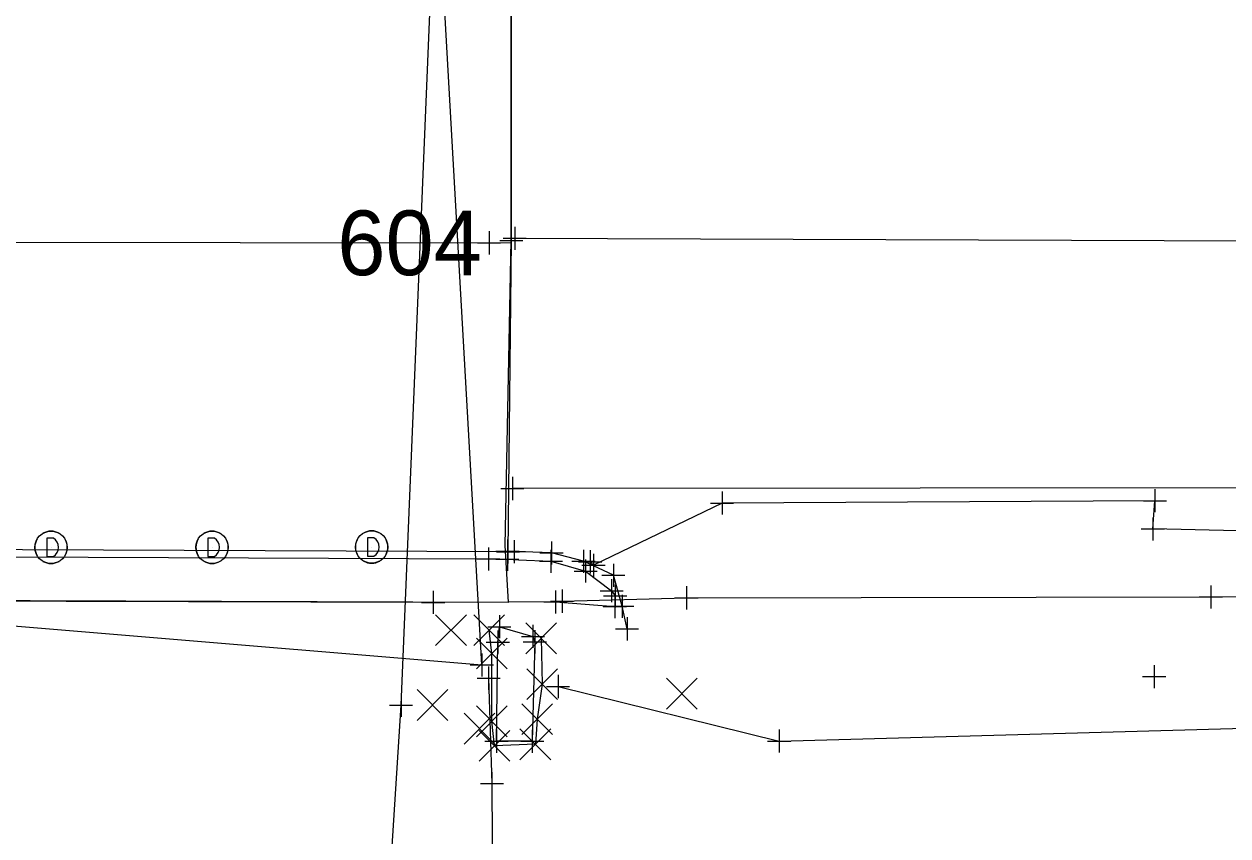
# Model space of a CAD drawing. Extents: x 146022 to 147632, y 437624 to 440659.
# Drawn here: x 147067.5 to 147119.5, y 438601.8 to 438636.9 of the extents above; entities that cross this region are included whole.
import ezdxf

# ---------------------------------------------------------------- set-up
doc = ezdxf.new("R2010")
doc.units = 0
for name, color, linetype in [('_CIVIL_CONSTRUCTION', 7, 'Continuous'), ('BR_P_Rail_Object', 7, 'Continuous'), ('Default', 7, 'Continuous'), ('DR_P_Paved_Gutter', 7, 'Continuous'), ('DR_X_Cells', 7, 'Continuous'), ('DT_X_Triangles', 7, 'Continuous'), ('GE_P_Alignment_100_Bearings', 7, 'Continuous'), ('GE_P_Alignment_100_Cardinal_Points', 7, 'Continuous'), ('GE_P_Alignment_100_Stations', 7, 'Continuous'), ('PF_X_Ground_Line', 7, 'Continuous'), ('PV_P_Curb', 7, 'Continuous'), ('RD_P_Anchor_Assembly', 7, 'Continuous'), ('RD_P_GR_Lt_Replaced', 7, 'Continuous'), ('SC_Scratch3', 7, 'Continuous'), ('SH_Text', 7, 'Continuous'), ('SV_X_Terrain_Boundary', 7, 'Continuous'), ('UT_X_Electric', 7, 'Continuous')]:
    doc.layers.add(name, color=color, linetype=linetype)

msp = doc.modelspace()

# ---------------------------------------------------------------- linework, layer by layer
at = {"layer": '_CIVIL_CONSTRUCTION'}
for p, q in [((147085.264, 438610.058), (147086.597, 438611.393)), ((147085.264, 438611.393), (147086.597, 438610.058)), ((147086.916, 438610.056), (147088.249, 438611.391)), ((147086.916, 438611.391), (147088.249, 438610.056)), ((147089.168, 438609.706), (147090.501, 438611.041)), ((147089.168, 438611.041), (147090.501, 438609.706)), ((147087.035, 438609.045), (147088.368, 438610.38)), ((147087.035, 438610.38), (147088.368, 438609.045)), ((147089.206, 438607.718), (147090.539, 438609.053)), ((147089.206, 438609.053), (147090.539, 438607.718)), ((147095.248, 438607.306), (147096.581, 438608.641)), ((147095.248, 438608.641), (147096.581, 438607.306)), ((147084.47, 438606.818), (147085.803, 438608.153)), ((147084.47, 438608.153), (147085.803, 438606.818)), ((147087.032, 438606.113), (147088.365, 438607.448)), ((147087.032, 438607.448), (147088.365, 438606.113)), ((147088.99, 438606.209), (147090.323, 438607.543)), ((147088.99, 438607.543), (147090.323, 438606.209)), ((147086.497, 438605.795), (147087.83, 438607.13)), ((147086.497, 438607.13), (147087.83, 438605.795)), ((147087.144, 438605.052), (147088.478, 438606.387)), ((147087.144, 438606.387), (147088.478, 438605.052)), ((147088.915, 438605.118), (147090.248, 438606.453)), ((147088.915, 438606.453), (147090.248, 438605.118))]:
    msp.add_line(p, q, dxfattribs=at)
at = {"layer": 'BR_P_Rail_Object'}
msp.add_lwpolyline([(147087.559, 438608.647), (147087.704, 438604.084), (147087.797, 438587.108)], dxfattribs=at)
at = {"layer": 'DR_P_Paved_Gutter'}
msp.add_lwpolyline([(147090.736, 438611.976), (147096.116, 438612.124), (147118.783, 438612.161), (147162.434, 438612.192), (147208.091, 438612.031), (147262.627, 438611.825), (147323.61, 438611.498), (147382.657, 438610.664), (147430.088, 438609.362), (147432.836, 438608.99), (147438.596, 438606.607), (147442.203, 438603.351)], dxfattribs=at)
at = {"layer": 'DR_X_Cells'}
msp.add_lwpolyline([(147053.205, 438613.153), (147055.234, 438611.895), (147087.267, 438609.219), (147085.148, 438646.666)], dxfattribs=at)
at = {"layer": 'DT_X_Triangles'}
for p, q in [((147068.641, 438614.307), (147068.641, 438614.307)), ((147068.641, 438614.307), (147068.641, 438614.307)), ((147068.641, 438614.307), (147068.641, 438614.307)), ((147068.641, 438614.307), (147068.641, 438614.307)), ((147068.641, 438614.307), (147068.641, 438614.307)), ((147075.603, 438614.308), (147075.603, 438614.308)), ((147075.603, 438614.308), (147075.603, 438614.308)), ((147075.603, 438614.308), (147075.603, 438614.308)), ((147075.603, 438614.308), (147075.603, 438614.308)), ((147075.603, 438614.308), (147075.603, 438614.308)), ((147082.502, 438614.32), (147082.502, 438614.32)), ((147082.502, 438614.32), (147082.502, 438614.32)), ((147082.502, 438614.32), (147082.502, 438614.32)), ((147082.502, 438614.32), (147082.502, 438614.32)), ((147082.502, 438614.32), (147082.502, 438614.32))]:
    msp.add_line(p, q, dxfattribs=at)
for centre in [(147068.641, 438614.307), (147075.603, 438614.308), (147082.502, 438614.32)]:
    msp.add_circle(centre, 0.7, dxfattribs=at)
at = {"layer": 'GE_P_Alignment_100_Bearings'}
msp.add_lwpolyline([(147087.958, 438610.21), (147088.024, 438610.873), (147089.477, 438610.454), (147089.556, 438610.221), (147089.448, 438605.916), (147087.898, 438605.923)], close=True, dxfattribs=at)
at = {"layer": 'GE_P_Alignment_100_Cardinal_Points'}
for points in [[(146886.273, 438614.58), (146893.974, 438614.564), (146939.097, 438614.385), (146982.973, 438614.237), (147025.25, 438614.063), (147087.547, 438613.803), (147088.31, 438613.791)], [(147093.543, 438610.779), (147093.338, 438611.757), (147092.953, 438613.099), (147091.66, 438613.705), (147090.28, 438614.065), (147088.661, 438614.121), (147088.406, 438614.145)], [(147088.311, 438613.791), (147088.371, 438613.79), (147088.845, 438613.769)], [(147088.85, 438613.769), (147090.253, 438613.705), (147091.753, 438613.282), (147092.878, 438612.431), (147093.031, 438612.203), (147093.016, 438611.748)]]:
    msp.add_lwpolyline(points, dxfattribs=at)
at = {"layer": 'GE_P_Alignment_100_Stations'}
for q in [(147088.432, 438611.938), (147093.016, 438611.748)]:
    msp.add_line((147090.448, 438611.946), q, dxfattribs=at)
msp.add_lwpolyline([(147088.417, 438611.938), (147085.161, 438611.927), (147048.137, 438612.028), (147009.735, 438612.191), (146980.437, 438612.254), (146944.113, 438612.41), (146906.055, 438612.508), (146890.588, 438612.592), (146885.707, 438612.644)], dxfattribs=at)
at = {"layer": 'PF_X_Ground_Line'}
for points in [[(147083.774, 438607.473), (147085.356, 438645.702), (147085.376, 438653.027), (147087.421, 438661.114), (147093.01, 438666.123), (147091.716, 438683.751), (147085.157, 438703.041), (147085.355, 438768.442), (147084.835, 438843.301), (147077.734, 438936.129), (147068.933, 439004.239), (147064.531, 439058.962), (147057.494, 439104.294)], [(147088.536, 438642.067), (147088.54, 438627.583), (147088.397, 438614.111)], [(147087.811, 438605.719), (147087.699, 438606.78), (147087.702, 438609.713), (147087.583, 438610.723)], [(147089.835, 438610.374), (147089.873, 438608.385), (147089.657, 438606.876)], [(147090.56, 438608.285), (147100.124, 438605.927), (147134.155, 438606.879), (147169.465, 438609.093), (147200.889, 438609.421), (147231.425, 438607.761), (147285.621, 438608.046), (147340.878, 438607.989), (147430.19, 438606.525), (147440.557, 438602.169), (147446.943, 438588.763), (147447.798, 438583.921), (147447.861, 438583.132)], [(147077.829, 438481.365), (147078.95, 438499.906), (147085.602, 438542.962), (147081.872, 438577.631), (147083.774, 438607.473)], [(147089.657, 438606.876), (147089.581, 438605.785), (147087.811, 438605.719)]]:
    msp.add_lwpolyline(points, dxfattribs=at)
at = {"layer": 'PV_P_Curb'}
msp.add_line((147087.577, 438627.48), (147088.513, 438627.489), dxfattribs=at)
for points in [[(146887.294, 438628.027), (146961.353, 438627.571), (147033.742, 438627.551), (147087.577, 438627.48)], [(147088.686, 438627.68), (147144.835, 438627.477)]]:
    msp.add_lwpolyline(points, dxfattribs=at)
at = {"layer": 'RD_P_Anchor_Assembly'}
for p, q in [((147088.54, 438628.083), (147088.54, 438627.083)), ((147088.686, 438628.18), (147088.686, 438627.18)), ((147087.577, 438627.98), (147087.577, 438626.98)), ((147088.04, 438627.583), (147089.04, 438627.583)), ((147088.186, 438627.68), (147089.186, 438627.68)), ((147088.54, 438627.583), (147088.54, 438627.583)), ((147088.686, 438627.68), (147088.686, 438627.68)), ((147087.077, 438627.48), (147088.077, 438627.48)), ((147087.577, 438627.48), (147087.577, 438627.48)), ((147088.586, 438617.354), (147088.586, 438616.354)), ((147088.086, 438616.854), (147089.086, 438616.854)), ((147088.586, 438616.854), (147088.586, 438616.854)), ((147097.654, 438616.724), (147097.654, 438615.724)), ((147116.368, 438616.824), (147116.368, 438615.824)), ((147097.154, 438616.224), (147098.154, 438616.224)), ((147097.654, 438616.224), (147097.654, 438616.224)), ((147115.868, 438616.324), (147116.868, 438616.324)), ((147116.368, 438616.324), (147116.368, 438616.324)), ((147116.276, 438615.601), (147116.276, 438614.601)), ((147115.776, 438615.101), (147116.776, 438615.101)), ((147116.276, 438615.101), (147116.276, 438615.101)), ((147088.373, 438614.648), (147088.373, 438613.648)), ((147088.373, 438614.648), (147088.373, 438613.648)), ((147088.397, 438614.611), (147088.397, 438613.611)), ((147088.661, 438614.621), (147088.661, 438613.621)), ((147088.661, 438614.621), (147088.661, 438613.621)), ((147090.28, 438614.565), (147090.28, 438613.565)), ((147090.28, 438614.565), (147090.28, 438613.565)), ((147087.547, 438614.303), (147087.547, 438613.303)), ((147087.873, 438614.148), (147088.873, 438614.148)), ((147087.873, 438614.148), (147088.873, 438614.148)), ((147087.897, 438614.111), (147088.897, 438614.111)), ((147088.161, 438614.121), (147089.161, 438614.121)), ((147088.161, 438614.121), (147089.161, 438614.121)), ((147088.371, 438614.29), (147088.371, 438613.29)), ((147088.373, 438614.148), (147088.373, 438614.148)), ((147088.373, 438614.148), (147088.373, 438614.148)), ((147088.397, 438614.111), (147088.397, 438614.111)), ((147088.661, 438614.121), (147088.661, 438614.121)), ((147088.661, 438614.121), (147088.661, 438614.121)), ((147089.78, 438614.065), (147090.78, 438614.065)), ((147089.78, 438614.065), (147090.78, 438614.065)), ((147090.253, 438614.205), (147090.253, 438613.205)), ((147090.28, 438614.065), (147090.28, 438614.065)), ((147090.28, 438614.065), (147090.28, 438614.065)), ((147091.66, 438614.205), (147091.66, 438613.205)), ((147091.66, 438614.205), (147091.66, 438613.205)), ((147091.948, 438614.182), (147091.948, 438613.182)), ((147092.094, 438614.029), (147092.094, 438613.029)), ((147087.047, 438613.803), (147088.047, 438613.803)), ((147087.547, 438613.803), (147087.547, 438613.803)), ((147087.871, 438613.79), (147088.871, 438613.79)), ((147088.371, 438613.79), (147088.371, 438613.79)), ((147089.753, 438613.705), (147090.753, 438613.705)), ((147090.253, 438613.705), (147090.253, 438613.705)), ((147091.16, 438613.705), (147092.16, 438613.705)), ((147091.16, 438613.705), (147092.16, 438613.705)), ((147091.448, 438613.682), (147092.448, 438613.682)), ((147091.594, 438613.529), (147092.594, 438613.529)), ((147091.66, 438613.705), (147091.66, 438613.705)), ((147091.66, 438613.705), (147091.66, 438613.705)), ((147091.753, 438613.782), (147091.753, 438612.782)), ((147091.948, 438613.682), (147091.948, 438613.682)), ((147092.094, 438613.529), (147092.094, 438613.529)), ((147092.953, 438613.599), (147092.953, 438612.599)), ((147092.953, 438613.599), (147092.953, 438612.599)), ((147091.253, 438613.282), (147092.253, 438613.282)), ((147091.753, 438613.282), (147091.753, 438613.282)), ((147092.453, 438613.099), (147093.453, 438613.099)), ((147092.453, 438613.099), (147093.453, 438613.099)), ((147092.953, 438613.099), (147092.953, 438613.099)), ((147092.953, 438613.099), (147092.953, 438613.099)), ((147090.736, 438612.476), (147090.736, 438611.476)), ((147092.878, 438612.931), (147092.878, 438611.931)), ((147093.031, 438612.703), (147093.031, 438611.703)), ((147096.116, 438612.624), (147096.116, 438611.624)), ((147118.783, 438612.661), (147118.783, 438611.661)), ((147085.161, 438612.427), (147085.161, 438611.427)), ((147089.948, 438611.946), (147090.948, 438611.946)), ((147090.236, 438611.976), (147091.236, 438611.976)), ((147090.448, 438612.446), (147090.448, 438611.446)), ((147090.448, 438611.946), (147090.448, 438611.946)), ((147090.736, 438611.976), (147090.736, 438611.976)), ((147092.378, 438612.431), (147093.378, 438612.431)), ((147092.531, 438612.203), (147093.531, 438612.203)), ((147092.878, 438612.431), (147092.878, 438612.431)), ((147093.016, 438612.248), (147093.016, 438611.248)), ((147093.031, 438612.203), (147093.031, 438612.203)), ((147093.338, 438612.257), (147093.338, 438611.257)), ((147093.338, 438612.257), (147093.338, 438611.257)), ((147095.616, 438612.124), (147096.616, 438612.124)), ((147096.116, 438612.124), (147096.116, 438612.124)), ((147118.283, 438612.161), (147119.283, 438612.161)), ((147118.783, 438612.161), (147118.783, 438612.161)), ((147084.661, 438611.927), (147085.661, 438611.927)), ((147085.161, 438611.927), (147085.161, 438611.927)), ((147092.516, 438611.748), (147093.516, 438611.748)), ((147092.838, 438611.757), (147093.838, 438611.757)), ((147092.838, 438611.757), (147093.838, 438611.757)), ((147093.016, 438611.748), (147093.016, 438611.748)), ((147093.338, 438611.757), (147093.338, 438611.757)), ((147093.338, 438611.757), (147093.338, 438611.757)), ((147088.024, 438611.373), (147088.024, 438610.373)), ((147089.477, 438610.954), (147089.477, 438609.954)), ((147093.543, 438611.279), (147093.543, 438610.279)), ((147093.543, 438611.279), (147093.543, 438610.279)), ((147087.524, 438610.873), (147088.524, 438610.873)), ((147087.958, 438610.71), (147087.958, 438609.71)), ((147088.024, 438610.873), (147088.024, 438610.873)), ((147088.977, 438610.454), (147089.977, 438610.454)), ((147089.477, 438610.454), (147089.477, 438610.454)), ((147089.556, 438610.721), (147089.556, 438609.721)), ((147093.043, 438610.779), (147094.043, 438610.779)), ((147093.043, 438610.779), (147094.043, 438610.779)), ((147093.543, 438610.779), (147093.543, 438610.779)), ((147093.543, 438610.779), (147093.543, 438610.779)), ((147087.458, 438610.21), (147088.458, 438610.21)), ((147087.958, 438610.21), (147087.958, 438610.21)), ((147089.056, 438610.221), (147090.056, 438610.221)), ((147089.556, 438610.221), (147089.556, 438610.221)), ((147087.267, 438609.719), (147087.267, 438608.719)), ((147086.767, 438609.219), (147087.767, 438609.219)), ((147087.267, 438609.219), (147087.267, 438609.219)), ((147087.559, 438609.147), (147087.559, 438608.147)), ((147116.333, 438609.216), (147116.333, 438608.216)), ((147087.059, 438608.647), (147088.059, 438608.647)), ((147087.559, 438608.647), (147087.559, 438608.647)), ((147090.06, 438608.285), (147091.06, 438608.285)), ((147090.56, 438608.785), (147090.56, 438607.785)), ((147090.56, 438608.285), (147090.56, 438608.285)), ((147115.833, 438608.716), (147116.833, 438608.716)), ((147116.333, 438608.716), (147116.333, 438608.716)), ((147083.774, 438607.973), (147083.774, 438606.973)), ((147083.274, 438607.473), (147084.274, 438607.473)), ((147083.774, 438607.473), (147083.774, 438607.473)), ((147087.898, 438606.423), (147087.898, 438605.423)), ((147089.448, 438606.416), (147089.448, 438605.416)), ((147100.124, 438606.427), (147100.124, 438605.427)), ((147087.398, 438605.923), (147088.398, 438605.923)), ((147087.898, 438605.923), (147087.898, 438605.923)), ((147088.948, 438605.916), (147089.948, 438605.916)), ((147089.448, 438605.916), (147089.448, 438605.916)), ((147099.624, 438605.927), (147100.624, 438605.927)), ((147100.124, 438605.927), (147100.124, 438605.927)), ((147087.704, 438604.584), (147087.704, 438603.584)), ((147087.204, 438604.084), (147088.204, 438604.084)), ((147087.704, 438604.084), (147087.704, 438604.084))]:
    msp.add_line(p, q, dxfattribs=at)
at = {"layer": 'RD_P_GR_Lt_Replaced'}
msp.add_lwpolyline([(147441.083, 438612.459), (147376.871, 438613.908), (147318.388, 438613.886), (147243.869, 438614.422), (147218.846, 438614.265), (147160.23, 438614.063), (147116.276, 438615.101), (147116.368, 438616.324), (147097.654, 438616.224), (147092.094, 438613.529), (147091.948, 438613.682)], dxfattribs=at)
at = {"layer": 'SC_Scratch3'}
msp.add_lwpolyline([(147441.537, 438616.003), (147377.935, 438616.36), (147319.327, 438616.539), (147244.051, 438616.808), (147219.362, 438616.863), (147159.113, 438616.912), (147088.586, 438616.854)], dxfattribs=at)
at = {"layer": 'SH_Text'}
msp.add_lwpolyline([(146885.966, 438642.868), (146926.812, 438642.691), (146985.277, 438642.496), (147039.933, 438642.254), (147088.536, 438642.067), (147088.54, 438627.583), (147088.397, 438614.111), (147046.407, 438614.279), (146992.08, 438614.464), (146931.328, 438614.71), (146885.67, 438614.858), (146885.649, 438627.845)], close=True, dxfattribs=at)
at = {"layer": 'SV_X_Terrain_Boundary'}
msp.add_lwpolyline([(146885.67, 438614.858), (146885.705, 438612.644), (147088.417, 438611.938), (147088.276, 438614.389), (147088.54, 438627.583), (147088.536, 438642.067), (147088.543, 438644.321), (147051.149, 438644.479), (146993.171, 438644.674), (146969.533, 438644.744), (146886.231, 438645.023), (146885.966, 438642.868), (146885.966, 438642.868), (146885.649, 438627.845)], close=True, dxfattribs=at)
at = {"layer": 'UT_X_Electric'}
for points in [[(147068.741, 438614.707), (147068.461, 438614.707), (147068.461, 438613.907), (147068.741, 438613.907)], [(147075.703, 438614.709), (147075.423, 438614.709), (147075.423, 438613.909), (147075.703, 438613.909)], [(147082.602, 438614.72), (147082.322, 438614.72), (147082.322, 438613.92), (147082.602, 438613.92)]]:
    msp.add_lwpolyline(points, dxfattribs=at)
for centre, radius, start, end in [((147068.641, 438614.307), 0.7, 150.0184, 209.9816), ((147068.641, 438614.307), 0.7, 60.0184, 120.0157), ((147068.486, 438614.307), 0.474, 302.5148, 57.4852), ((147068.641, 438614.307), 0.7, 330.0184, 29.9816), ((147075.603, 438614.308), 0.7, 150.0184, 209.9816), ((147075.603, 438614.308), 0.7, 60.0184, 120.0157), ((147075.448, 438614.308), 0.474, 302.5148, 57.4852), ((147075.603, 438614.308), 0.7, 330.0184, 29.9816), ((147082.502, 438614.32), 0.7, 150.0184, 209.9816), ((147082.502, 438614.32), 0.7, 60.0184, 120.0157), ((147082.347, 438614.32), 0.474, 302.5148, 57.4852), ((147082.502, 438614.32), 0.7, 330.0184, 29.9816), ((147068.641, 438614.307), 0.7, 239.9843, 299.9816), ((147075.603, 438614.308), 0.7, 239.9843, 299.9816), ((147082.502, 438614.32), 0.7, 239.9843, 299.9816)]:
    msp.add_arc(centre, radius, start, end, dxfattribs=at)

# ---------------------------------------------------------------- texts
at = {"layer": 'Default'}
msp.add_text('604', height=2.8, dxfattribs=at).set_placement((147081.017, 438626.08))

doc.saveas('drawing.dxf')
